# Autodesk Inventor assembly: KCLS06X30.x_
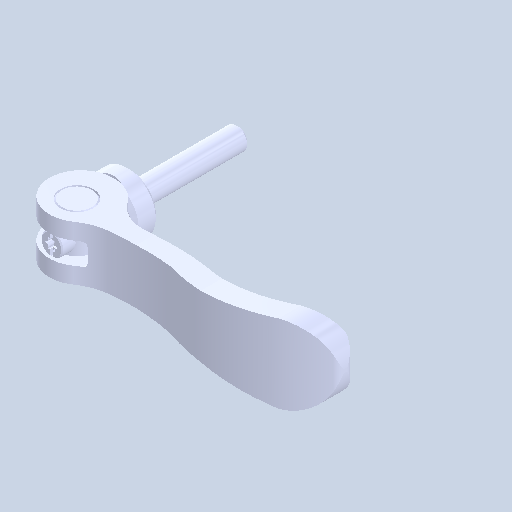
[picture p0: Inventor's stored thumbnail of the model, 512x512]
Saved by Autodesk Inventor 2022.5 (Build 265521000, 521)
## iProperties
Created: 2024-08
Part Number: KCLS06X30.x_
Document SubType Name: Assembly
Designer: ImaoCorp
Author: ImaoCorp
Sending System: SOLIDWORKS 2022-2022290
MC: AMD64
MC_MODEL: Intel64 Family 6 Model 60 Stepping 3, GenuineIntel
OS: Windows_NT
FRU: Parasolid Version 33.1, build 260,  4-25-2022
FORMAT: text
GUISE: transmit
KEY: FILEKCLS06X30.x_t
DATE: Thu Aug 29 10:54:54 2024
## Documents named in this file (5)
- Y:\5.更新分\2024年対応\1001_KCL\データ\kcls06x30\KCLS06X30.x_.iam
- Y:\5.更新分\2024年対応\1001_KCL\データ\kcls06x30\KCLS06X30_01.ipt
- Y:\5.更新分\2024年対応\1001_KCL\データ\kcls06x30\KCLS06X30_02.ipt
- Y:\5.更新分\2024年対応\1001_KCL\データ\kcls06x30\KCLS06X30_03.ipt
- Y:\5.更新分\2024年対応\1001_KCL\データ\kcls06x30\KCLS06X30_04.ipt
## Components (4 placed, 4 different names)
1. KCLS06X30_01
2. KCLS06X30_02
3. KCLS06X30_03
4. KCLS06X30_04
